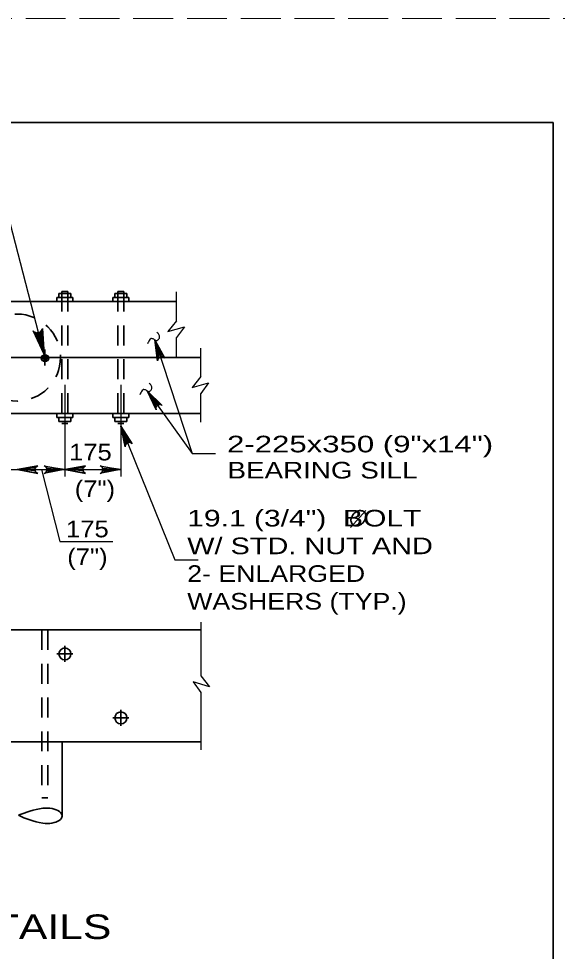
# Model space of a CAD drawing. Extents: x -6.4 to 73.1, y -66 to 0.
# Drawn here: x 29.39 to 33.28, y -6.73 to 0 of the extents above; entities that cross this region are included whole.
import ezdxf
from ezdxf.enums import TextEntityAlignment as Align

# ---------------------------------------------------------------- set-up
doc = ezdxf.new("R2010")
doc.units = 0
doc.header["$LTSCALE"] = 0.048
doc.linetypes.add('LONG_DASHED', pattern=[7.5, 6, -1.5])
doc.linetypes.add('MEDIUM_DASHED', pattern=[4.5, 3, -1.5])
for name, color, linetype, lineweight in [('1', 7, 'Continuous', 13), ('4', 7, 'Continuous', 25), ('5', 7, 'Continuous', 25), ('52', 7, 'Continuous', 25), ('63', 7, 'LONG_DASHED', 13)]:
    doc.layers.add(name, color=color, linetype=linetype, lineweight=lineweight)

msp = doc.modelspace()

# ---------------------------------------------------------------- hatches: boundary and pattern name
at = {"layer": '5'}
msp.add_hatch(color=256, dxfattribs=at).paths.add_polyline_path([(30.13075, -2.9415), (30.16592, -3.05467), (30.18417, -3.04725)])

# ---------------------------------------------------------------- linework, layer by layer
at = {"layer": '1', "lineweight": 35}
msp.add_lwpolyline([(1.75, -21.25), (33.25, -21.25), (33.25, -0.75), (1.75, -0.75)], close=True, dxfattribs=at)
at = {"layer": '4', "lineweight": 35}
for p, q in [((29.68383, -2.014), (29.68383, -1.98517)), ((29.68383, -1.98517), (29.77033, -1.98517)), ((29.7055, -1.97075), (29.74875, -1.97075)), ((29.77033, -2.014), (29.77033, -1.98517)), ((29.78475, -2.04283), (29.78475, -2.014)), ((30.0875, -2.014), (30.0875, -1.98517)), ((30.0875, -1.98517), (30.174, -1.98517)), ((30.10917, -1.97075), (30.15242, -1.97075)), ((30.174, -2.014), (30.174, -1.98517)), ((30.18842, -2.04283), (30.18842, -2.014)), ((30.53308, -2.04283), (24.3075, -2.04283)), ((29.58292, -2.38892), (29.58292, -2.50425)), ((30.7075, -2.44658), (24.133, -2.44658)), ((29.64058, -2.44658), (29.52525, -2.44658)), ((30.7075, -2.85025), (24.133, -2.85025)), ((29.66942, -2.85025), (29.66942, -2.87908)), ((29.66942, -2.87908), (29.78475, -2.87908)), ((29.77033, -2.87908), (29.77033, -2.90792)), ((29.78475, -2.85025), (29.78475, -2.87908)), ((30.07308, -2.85025), (30.07308, -2.87908)), ((30.07308, -2.87908), (30.18842, -2.87908)), ((30.174, -2.87908), (30.174, -2.90792)), ((30.18842, -2.85025), (30.18842, -2.87908)), ((29.7055, -2.92233), (29.74875, -2.92233)), ((30.10917, -2.92233), (30.15242, -2.92233)), ((30.7075, -4.41358), (24.133, -4.41358)), ((29.72708, -4.52892), (29.72708, -4.64425)), ((29.78475, -4.58658), (29.66942, -4.58658)), ((30.18842, -5.048), (30.07308, -5.048)), ((30.13075, -4.99033), (30.13075, -5.10567)), ((30.7075, -5.221), (24.133, -5.221)), ((29.70658, -5.221), (29.70658, -5.75683)), ((29.56125, -5.62467), (29.6045, -5.62467))]:
    msp.add_line(p, q, dxfattribs=at)
at = {"layer": '4', "linetype": 'MEDIUM_DASHED', "lineweight": 35}
for p, q in [((29.7055, -1.97075), (29.7055, -2.92233)), ((29.74875, -1.97075), (29.74875, -2.92233)), ((30.10917, -1.97075), (30.10917, -2.92233)), ((30.15242, -1.97075), (30.15242, -2.92233)), ((29.56125, -4.41358), (29.56125, -5.62467)), ((29.6045, -4.41358), (29.6045, -5.62467))]:
    msp.add_line(p, q, dxfattribs=at)
at = {"layer": '4'}
for p, q in [((30.53308, -2.18067), (30.53308, -1.97208)), ((30.53308, -2.18067), (30.46967, -2.25858)), ((30.46967, -2.25858), (30.58892, -2.22483)), ((30.58892, -2.22483), (30.53308, -2.30142)), ((30.53308, -2.44658), (30.53308, -2.30142)), ((30.7075, -2.58433), (30.7075, -2.37925)), ((30.7075, -2.9135), (30.7075, -2.70508)), ((30.7075, -4.35592), (30.7075, -4.74483)), ((30.7075, -4.74483), (30.77083, -4.82283)), ((30.65158, -4.789), (30.7075, -4.86558)), ((30.77083, -4.82283), (30.65158, -4.789)), ((30.7075, -4.86558), (30.7075, -5.27867))]:
    msp.add_line(p, q, dxfattribs=at)
at = {"layer": '4', "lineweight": 35}
for points in [[(29.66942, -2.04283), (29.66942, -2.014), (29.78475, -2.014)], [(30.07308, -2.04283), (30.07308, -2.014), (30.18842, -2.014)], [(29.68383, -2.87908), (29.68383, -2.90792), (29.77033, -2.90792)], [(30.0875, -2.87908), (30.0875, -2.90792), (30.174, -2.90792)]]:
    msp.add_lwpolyline(points, dxfattribs=at)
at = {"layer": '4'}
msp.add_lwpolyline([(30.7075, -2.58433), (30.64408, -2.66225), (30.76333, -2.6285), (30.7075, -2.70508)], dxfattribs=at)
at = {"layer": '4', "linetype": 'MEDIUM_DASHED', "lineweight": 35}
msp.add_circle((29.381, -2.44662), 0.31393, dxfattribs=at)
at = {"layer": '4', "lineweight": 35}
for centre in [(29.72702, -4.58663), (30.13072, -5.04799)]:
    msp.add_circle(centre, 0.04325, dxfattribs=at)
for centre, major_axis, start_param, end_param in [((29.70392, -5.91367), (0.44359, -0.00737), 1.8903203, 2.3561945), ((29.59541, -5.75499), (0.11112, -0.00185), 4.4555879, 8.1107827), ((29.70913, -5.6), (0.44359, -0.00737), 3.9269908, 4.392865)]:
    msp.add_ellipse(centre, major_axis=major_axis, ratio=0.5, start_param=start_param, end_param=end_param, dxfattribs=at)
at = {"layer": '5'}
for p, q in [((30.37508, -2.31892), (30.64608, -3.13883)), ((29.72708, -2.64358), (29.72708, -3.30517)), ((30.13075, -2.64358), (30.13075, -3.30517)), ((30.13075, -2.9415), (30.52108, -3.90617)), ((27.42025, -3.25558), (30.13075, -3.25558)), ((30.52108, -3.90617), (30.68783, -3.90617))]:
    msp.add_line(p, q, dxfattribs=at)
at = {"layer": '5', "lineweight": 35}
msp.add_line((31.78767, -3.67258), (31.89967, -3.55), dxfattribs=at)
at = {"layer": '5'}
for points in [[(29.57725, -2.425), (29.33125, -1.47317), (28.82008, -1.47317)], [(29.57725, -2.425), (29.49675, -2.25325), (29.50342, -2.259), (29.51, -2.26467), (29.517, -2.26667), (29.524, -2.26875), (29.53025, -2.26817), (29.53658, -2.26767), (29.54242, -2.26508), (29.54817, -2.2625), (29.55333, -2.25733), (29.55842, -2.25217), (29.56142, -2.244), (29.5645, -2.23575), (29.57725, -2.425), (29.56142, -2.244), (29.55842, -2.25217), (29.57725, -2.425), (29.55333, -2.25733), (29.54817, -2.2625), (29.57725, -2.425), (29.54242, -2.26508), (29.53658, -2.26767), (29.57725, -2.425), (29.53025, -2.26817), (29.524, -2.26875), (29.57725, -2.425), (29.517, -2.26667), (29.51, -2.26467), (29.57725, -2.425), (29.50342, -2.259)], [(30.37508, -2.31892), (30.44842, -2.45175), (30.43725, -2.44333), (30.42592, -2.44083), (30.41592, -2.44233), (30.40692, -2.44708), (30.39925, -2.45592), (30.39533, -2.46925), (30.37508, -2.31892), (30.39925, -2.45592), (30.40692, -2.44708), (30.37508, -2.31892), (30.41592, -2.44233), (30.42592, -2.44083), (30.37508, -2.31892), (30.43725, -2.44333)], [(30.3195, -2.68717), (30.64608, -3.13883), (30.81283, -3.13883)], [(30.3195, -2.68717), (30.4295, -2.79167), (30.41633, -2.787), (30.40475, -2.78808), (30.39567, -2.7925), (30.38858, -2.79975), (30.38392, -2.81042), (30.38425, -2.82442), (30.3195, -2.68717), (30.38392, -2.81042), (30.38858, -2.79975), (30.3195, -2.68717), (30.39567, -2.7925), (30.40475, -2.78808), (30.3195, -2.68717), (30.41633, -2.787)], [(30.13075, -2.9415), (30.21258, -3.06925), (30.20092, -3.06158), (30.18942, -3.05983), (30.1795, -3.062), (30.17092, -3.06733), (30.16383, -3.07658), (30.16075, -3.09025), (30.13075, -2.9415), (30.16383, -3.07658), (30.17092, -3.06733), (30.13075, -2.9415), (30.1795, -3.062), (30.18942, -3.05983), (30.13075, -2.9415), (30.20092, -3.06158)], [(29.38108, -3.25558), (29.53025, -3.28358), (29.51875, -3.27558), (29.51283, -3.26558), (29.51108, -3.25558), (29.51283, -3.24558), (29.51875, -3.23558), (29.53025, -3.22758), (29.38108, -3.25558), (29.51875, -3.23558), (29.51283, -3.24558), (29.38108, -3.25558), (29.51108, -3.25558), (29.51283, -3.26558), (29.38108, -3.25558), (29.51875, -3.27558)], [(29.72708, -3.25558), (29.57792, -3.28358), (29.58942, -3.27558), (29.59533, -3.26558), (29.59708, -3.25558), (29.59533, -3.24558), (29.58942, -3.23558), (29.57792, -3.22758), (29.72708, -3.25558), (29.58942, -3.23558), (29.59533, -3.24558), (29.72708, -3.25558), (29.59708, -3.25558), (29.59533, -3.26558), (29.72708, -3.25558), (29.58942, -3.27558)], [(29.72708, -3.25558), (29.87625, -3.28358), (29.86475, -3.27558), (29.85883, -3.26558), (29.85708, -3.25558), (29.85883, -3.24558), (29.86475, -3.23558), (29.87625, -3.22758), (29.72708, -3.25558), (29.86475, -3.23558), (29.85883, -3.24558), (29.72708, -3.25558), (29.85708, -3.25558), (29.85883, -3.26558), (29.72708, -3.25558), (29.86475, -3.27558)], [(30.13075, -3.25558), (29.98158, -3.28358), (29.99308, -3.27558), (29.999, -3.26558), (30.00075, -3.25558), (29.999, -3.24558), (29.99308, -3.23558), (29.98158, -3.22758), (30.13075, -3.25558), (29.99308, -3.23558), (29.999, -3.24558), (30.13075, -3.25558), (30.00075, -3.25558), (29.999, -3.26558), (30.13075, -3.25558), (29.99308, -3.27558)]]:
    msp.add_lwpolyline(points, dxfattribs=at)
msp.add_lwpolyline([(30.13075, -2.9415), (30.16592, -3.05467), (30.18417, -3.04725)], close=True, dxfattribs=at)
for radius in [0.02667, 0.02, 0.01333, 0.00667]:
    msp.add_circle((29.58283, -2.45109), radius, dxfattribs=at)
for centre, radius, start, end in [((30.37087, -2.30084), 0.04045, 39.8006, 60.65202), ((30.38116, -2.29227), 0.02706, 14.23512, 39.8006), ((30.33737, -2.30338), 0.07225, 5.70959, 14.23512), ((30.41015, -2.37546), 0.09068, 153.43899, 161.96079), ((30.40147, -2.37113), 0.08098, 144.4201, 153.43899), ((30.46639, -2.41757), 0.1608, 138.37148, 144.4201), ((30.3507, -2.31475), 0.00602, 106.72409, 138.37148), ((30.35105, -2.3159), 0.00722, 77.46905, 106.72408), ((30.33593, -2.38392), 0.0769, 68.59546, 77.46905), ((30.35335, -2.33947), 0.02915, 48.06467, 68.59546), ((30.38771, -2.30123), 0.02225, 228.06467, 251.60538), ((30.3865, -2.30484), 0.01844, 251.60538, 287.10557), ((30.38525, -2.30077), 0.0227, 287.10557, 318.99925), ((30.37774, -2.29424), 0.03266, 318.99925, 333.43899), ((30.38651, -2.29862), 0.02285, 333.43899, 350.72014), ((30.38591, -2.29852), 0.02346, 350.72014, 5.70959), ((30.34589, -2.73938), 0.08098, 144.4201, 153.43899), ((30.41081, -2.78583), 0.1608, 138.37148, 144.4201), ((30.29512, -2.68301), 0.00602, 106.72409, 138.37148), ((30.29546, -2.68416), 0.00722, 77.46905, 106.72408), ((30.28034, -2.75218), 0.0769, 68.59546, 77.46905), ((30.29777, -2.70773), 0.02915, 48.06467, 68.59546), ((30.33212, -2.66949), 0.02225, 228.06467, 251.60538), ((30.33092, -2.6731), 0.01844, 251.60538, 287.10557), ((30.31529, -2.6691), 0.04045, 39.8006, 60.65202), ((30.32966, -2.66903), 0.0227, 287.10557, 318.99925), ((30.32558, -2.66052), 0.02706, 14.23512, 39.8006), ((30.32215, -2.6625), 0.03266, 318.99925, 333.43899), ((30.33092, -2.66688), 0.02285, 333.43899, 350.72014), ((30.28178, -2.67164), 0.07225, 5.70959, 14.23512), ((30.33032, -2.66678), 0.02346, 350.72014, 5.70959), ((30.35457, -2.74372), 0.09068, 153.43899, 161.96079)]:
    msp.add_arc(centre, radius, start, end, dxfattribs=at)
at = {"layer": '5', "lineweight": 35}
msp.add_spline([(31.888, -3.56208), (31.87925, -3.55525), (31.8705, -3.55283), (31.8595, -3.55183), (31.85325, -3.55183), (31.8425, -3.55433), (31.83267, -3.55883), (31.82575, -3.56275), (31.8125, -3.57333), (31.80217, -3.58683), (31.79592, -3.5995), (31.79225, -3.61108), (31.79117, -3.62183), (31.79225, -3.63108), (31.79675, -3.64425), (31.8015, -3.65108), (31.81117, -3.65833), (31.82567, -3.66183), (31.84217, -3.66133), (31.863, -3.65183), (31.87825, -3.63875), (31.88975, -3.62283), (31.89725, -3.60625), (31.89975, -3.58783), (31.8965, -3.576), (31.8885, -3.56208)], degree=3, dxfattribs=at)
at = {"layer": '52'}
msp.add_lwpolyline([(29.55783, -3.25558), (29.69025, -3.7745), (30.07192, -3.7745)], dxfattribs=at)
at = {"layer": '63'}
msp.add_lwpolyline([(0, -22), (34, -22), (34, 0), (0, 0)], close=True, dxfattribs=at)

# ---------------------------------------------------------------- texts
at = {"layer": '5'}
for s, width, p in [('2-225x350 (9"x14")', 1.4, (30.89708, -3.13108)), ('BEARING SILL', 1.25, (30.90008, -3.31983)), ('19.1 (3/4")  BOLT', 1.35, (30.6095, -3.66633)), ('W/ STD. NUT AND', 1.3, (30.6095, -3.86633)), ('2- ENLARGED', 1.2, (30.6095, -4.06633)), ('WASHERS (TYP.)', 1.2, (30.6095, -4.26633))]:
    msp.add_text(s, height=0.12, dxfattribs=dict(at, width=width)).set_placement(p)
for s, height, width, p in [('175', 0.12, 1.15, (29.91067, -3.1895)), ('(7")', 0.12, 1.15, (29.94317, -3.4535)), ('175', 0.12, 1.15, (29.88875, -3.7445)), ('(7")', 0.12, 1.15, (29.88925, -3.9445)), ('BEARING SILL SPLICE DETAILS', 0.1772, 1.3, (27.73379, -6.64458))]:
    msp.add_text(s, height=height, dxfattribs=dict(at, width=width)).set_placement(p, align=Align.CENTER)

doc.saveas('drawing.dxf')
